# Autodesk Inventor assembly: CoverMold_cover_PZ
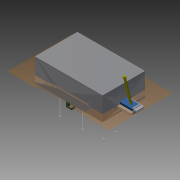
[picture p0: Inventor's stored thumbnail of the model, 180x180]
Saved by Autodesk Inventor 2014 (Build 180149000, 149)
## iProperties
Created: 2009-12
Part Number: CoverMold_cover_PZ
Document SubType Name: Assembly
Designer: gaom
Author: gaom
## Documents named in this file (15)
- C:\Users\iTools\Desktop\tutorial files\Mold\CoverMold\Cover Mold\CoverMold_cover_PZ.iam
- C:\Users\iTools\Desktop\tutorial files\Mold\CoverMold\Cover Mold\CoverMold_cover_MP.ipt
- C:\Users\iTools\Desktop\tutorial files\Mold\CoverMold\Cover Mold\CoverMold_cover_WP.ipt
- C:\Users\iTools\Desktop\tutorial files\Mold\CoverMold\Cover Mold\CoverMold_cover_CR_Base.ipt
- C:\Users\iTools\Desktop\tutorial files\Mold\CoverMold\Cover Mold\CoverMold_cover_CV_Base.ipt
- C:\Users\iTools\Desktop\tutorial files\Mold\CoverMold\Cover Mold\CoverMold_cover_IN1_Base.ipt
- C:\Users\iTools\Desktop\tutorial files\Mold\CoverMold\Cover Mold\CoverMold_cover_IN1_1_1.ipt
- C:\Users\iTools\Desktop\tutorial files\Mold\CoverMold\Cover Mold\Ejectors\DME_AH\EP Group1.0\CoverMold_cover_EP Group1_EP1.ipt
- C:\Users\iTools\Desktop\tutorial files\Mold\CoverMold\Cover Mold\Ejectors\DME_AH\EP Group1.0\CoverMold_cover_EP Group1_EP2.ipt
- C:\Users\iTools\Desktop\tutorial files\Mold\CoverMold\Cover Mold\Ejectors\DME_AH\EP Group1.0\CoverMold_cover_EP Group1_EP3.ipt
- C:\Users\iTools\Desktop\tutorial files\Mold\CoverMold\Cover Mold\Ejectors\DME_AH\EP Group1.0\CoverMold_cover_EP Group1_EP4.ipt
- C:\Users\iTools\Desktop\tutorial files\Mold\CoverMold\Cover Mold\Ejectors\DME_AH\EP Group1.0\CoverMold_cover_EP Group1_EP5.ipt
- C:\Users\iTools\Desktop\tutorial files\Mold\CoverMold\Cover Mold\Ejectors\DME_AH\EP Group1.0\CoverMold_cover_EP Group1_EP6.ipt
- C:\Users\iTools\Desktop\tutorial files\Mold\CoverMold\Cover Mold\Sliders\GENERIC_Generic Single Locking 1 1\CoverMold_cover_SA1.iam
- C:\Users\iTools\Desktop\tutorial files\Mold\CoverMold\Cover Mold\Lifters\DME_Flat Core Blades 2\CoverMold_cover_LA1.iam
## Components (14 placed, 14 different names)
1. CoverMold_cover_MP:1 — Flush:1, Flush:2, Flush:3, Flush:4, Flush:5, Flush:6
2. CoverMold_cover_WP:1 — Flush:4, Flush:5, Flush:6
3. CoverMold_cover_CR_Base:1 — Flush:7, Flush:8, Flush:9
4. CoverMold_cover_CV_Base:1 — Flush:10, Flush:11, Flush:12
5. CoverMold_cover_IN1_Base:1 — Flush:13, Flush:14, Flush:15, Flush:16, Flush:17, Flush:18
6. CoverMold_cover_IN1_1_1:1 — Flush:16, Flush:17, Flush:18
7. CoverMold_cover_EP Group1_EP1:1 — Mate:1, Flush:19, Angle:1
8. CoverMold_cover_EP Group1_EP2:1 — Mate:2, Flush:20, Angle:2
9. CoverMold_cover_EP Group1_EP3:1 — Mate:3, Flush:21, Angle:3
10. CoverMold_cover_EP Group1_EP4:1 — Mate:4, Flush:22, Angle:4
11. CoverMold_cover_EP Group1_EP5:1 — Mate:5, Flush:23, Angle:5
12. CoverMold_cover_EP Group1_EP6:1 — Mate:6, Flush:24, Angle:6
13. CoverMold_cover_SA1:1 [sub-assembly]
14. CoverMold_cover_LA1:1 [sub-assembly]
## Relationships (36: Flush 24, Mate 6, Angle 6)
- Flush:1: CoverMold_cover_MP:1
- Flush:2: CoverMold_cover_MP:1
- Flush:3: CoverMold_cover_MP:1
- Flush:4: CoverMold_cover_MP:1 ↔ CoverMold_cover_WP:1
- Flush:5: CoverMold_cover_MP:1 ↔ CoverMold_cover_WP:1
- Flush:6: CoverMold_cover_MP:1 ↔ CoverMold_cover_WP:1
- Flush:7: CoverMold_cover_CR_Base:1
- Flush:8: CoverMold_cover_CR_Base:1
- Flush:9: CoverMold_cover_CR_Base:1
- Flush:10: CoverMold_cover_CV_Base:1
- Flush:11: CoverMold_cover_CV_Base:1
- Flush:12: CoverMold_cover_CV_Base:1
- Flush:13: CoverMold_cover_IN1_Base:1
- Flush:14: CoverMold_cover_IN1_Base:1
- Flush:15: CoverMold_cover_IN1_Base:1
- Flush:16: CoverMold_cover_IN1_Base:1 ↔ CoverMold_cover_IN1_1_1:1
- Flush:17: CoverMold_cover_IN1_Base:1 ↔ CoverMold_cover_IN1_1_1:1
- Flush:18: CoverMold_cover_IN1_Base:1 ↔ CoverMold_cover_IN1_1_1:1
- Mate:1: CoverMold_cover_EP Group1_EP1:1
- Flush:19: CoverMold_cover_EP Group1_EP1:1
- Angle:1: CoverMold_cover_EP Group1_EP1:1
- Mate:2: CoverMold_cover_EP Group1_EP2:1
- Flush:20: CoverMold_cover_EP Group1_EP2:1
- Angle:2: CoverMold_cover_EP Group1_EP2:1
- Mate:3: CoverMold_cover_EP Group1_EP3:1
- Flush:21: CoverMold_cover_EP Group1_EP3:1
- Angle:3: CoverMold_cover_EP Group1_EP3:1
- Mate:4: CoverMold_cover_EP Group1_EP4:1
- Flush:22: CoverMold_cover_EP Group1_EP4:1
- Angle:4: CoverMold_cover_EP Group1_EP4:1
- Mate:5: CoverMold_cover_EP Group1_EP5:1
- Flush:23: CoverMold_cover_EP Group1_EP5:1
- Angle:5: CoverMold_cover_EP Group1_EP5:1
- Mate:6: CoverMold_cover_EP Group1_EP6:1
- Flush:24: CoverMold_cover_EP Group1_EP6:1
- Angle:6: CoverMold_cover_EP Group1_EP6:1
